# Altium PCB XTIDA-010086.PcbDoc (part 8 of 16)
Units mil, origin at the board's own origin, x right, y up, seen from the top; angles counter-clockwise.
Board outline 14763.78 x 8267.72 mil, 6 copper layers (Top Layer, GND Layer, Signal Layer 1, Signal Layer 2, Power Layer, Bottom Layer), stack 62 mil thick; 1933 components, 1002 nets, 4886 pads, 6482 vias.
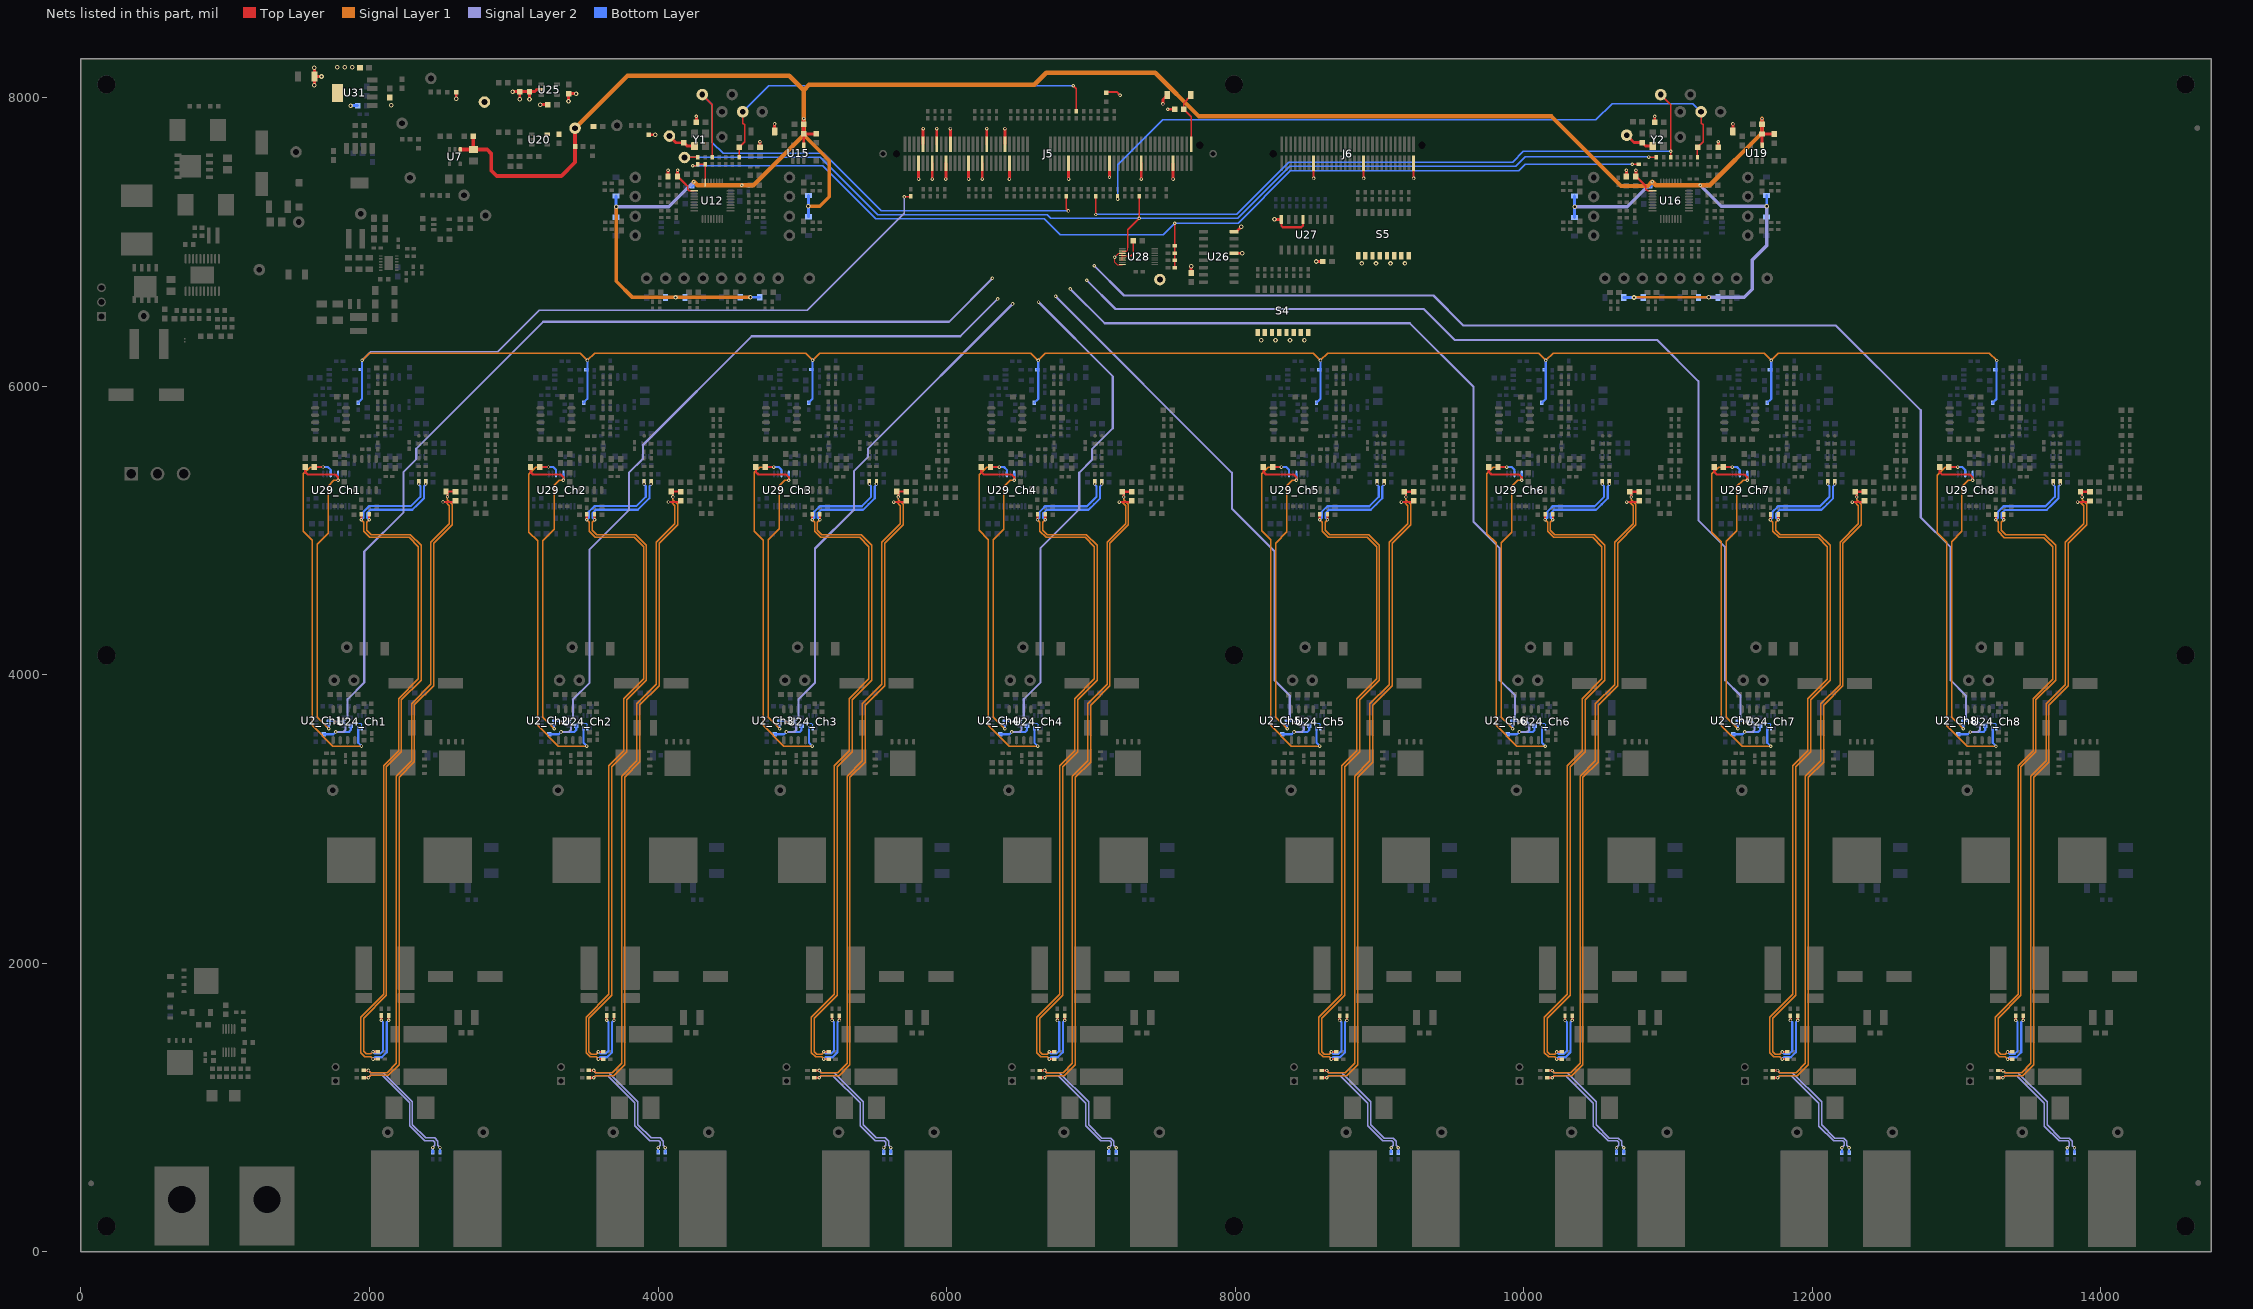
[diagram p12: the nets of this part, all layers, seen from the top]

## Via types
v1: diameter 32, hole 16, Top Layer to Bottom Layer, tented both sides, 4685 vias
v2: diameter 24, hole 12, Top Layer to Bottom Layer, tented both sides, 1013 vias
v3: diameter 32, hole 16, Top Layer to Bottom Layer, 728 vias
v4: diameter 19.68, hole 7.87, Top Layer to Bottom Layer, 40 vias
v5: diameter 214.57, hole 140, Top Layer to Bottom Layer, 16 vias

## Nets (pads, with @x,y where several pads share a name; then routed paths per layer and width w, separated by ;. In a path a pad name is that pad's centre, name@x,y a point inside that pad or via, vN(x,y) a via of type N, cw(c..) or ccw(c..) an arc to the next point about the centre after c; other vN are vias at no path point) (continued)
AVDD: C79.1 C80.1 C100.1 C101.1 C103.1 C129.1 D12.1 D16.1 D19.1 D20.1 D21.1 D22.1 D23.1 D24.1 D25.1 D26.1 D27.1 D28.1 D29.1 D30.1 D31.1 D32.1 R115.1 R119.1 R146.1 R150.1 R177.2 R180.1 R181.2 R184.2 R203.1 TP24.1 U7.1 U15.4 U19.4 U20.5 | length 18806.3
  Top Layer w20: v2(5009.33,7853.48) C79.1@5009.33,7813.48 C80.1@5009.33,7747.48 ; U15.4@5009.73,7668.61 5009.73,7747.08 C80.1@5009.33,7747.48 ; R177.2@5096,7748.5 5094.98,7747.48 C80.1@5009.33,7747.48 ; v2(11651.01,7853.19) C100.1@11651.01,7813.19 11651.01,7747.19 C101.1@11651.41,7746.79 ; U19.4@11651.41,7668.32 C101.1@11651.41,7746.79 ; R181.2@11737.06,7746.79 C101.1@11651.41,7746.79
  Top Layer w25: U7.1@2629.4,7639.52 C129.1@2719.8,7639.52 ; R184.2@2720.5,7731.32 2720.5,7640.21 C129.1@2719.8,7639.52 ; TP24.1@3425,7787 R180.1@3425,7660 3425,7550.31 3330.69,7456 2882.85,7456 2843,7495.85 2843,7612 2815.68,7639.32 C129.1@2720,7639.32 C129.1@2719.8,7639.52
  Signal Layer 1 w20: v1(10763.53,6613.86) 10764.89,6615.22 v1(11282.02,6615.22)
  Signal Layer 1 w25: v1(3710,7243) 3710,6727 3822.83,6614.17 v1(4121.83,6614.17) 4123.19,6615.54 v1(4640.32,6615.54) ; 5009.33,7740.33 5186,7563.66 5186,7311 5120.5,7245.5 v1(5041.93,7245.5)
  Signal Layer 1 w30: TP24.1@3425,7787 3788,8150 4910,8150 5009.33,8050.67 ; v2(4248.53,7416.63) 4272.91,7392.26 v2(4580.91,7392.26) 4661.26,7392.26 5009.33,7740.33 v2(5009.33,7853.48) 5009.33,8050.67 ; v2(11651.01,7853.19) 11651.01,7754.01 11288.94,7391.94 v2(11222.61,7391.94) 10914.61,7391.94 v2(10890.23,7416.32) 10860.91,7387 10674,7387 10192,7869 7749.64,7869 7446.64,8172 6691,8172 6607,8088 5046.66,8088 5009.33,8050.67
  Signal Layer 2 w25: v1(3710,7243) 4074.89,7243 v2(4248.53,7416.63) ; v1(10352.7,7241.69) 10717.6,7241.69 v2@10891.23,7415.32 ; v2(11222.61,7391.94) 11369.37,7245.18 v1(11683.63,7245.18) 11683.63,6973.63 11584,6874 11584,6671 11528.22,6615.22 v1(11282.02,6615.22)
  Bottom Layer w20: D16.1@3710,7170.47 v1(3710,7243) D12.1@3710,7318.06 ; D19.1@4051.05,6614.17 v1(4121.83,6614.17) D20.1@4186.24,6614.17 ; R115.1@4236.15,7382.63 4248.53,7395.01 v2(4248.53,7416.63) ; D21.1@4569.55,6615.54 v1(4640.32,6615.54) D22.1@4704.74,6615.54 ; v2(4580.91,7392.26) R119.1@4624.53,7392.26 ; D23.1@5041.93,7172.96 v1(5041.93,7245.5) D24.1@5041.93,7320.56 ; D26.1@10352.7,7169.15 v1(10352.7,7241.69) D25.1@10352.7,7316.75 ; D27.1@10692.75,6613.86 v1(10763.53,6613.86) D28.1@10827.94,6613.86 ; R146.1@10877.85,7382.32 10890.23,7394.7 v2(10890.23,7416.32) ; D29.1@11211.25,6615.22 v1(11282.02,6615.22) D30.1@11346.44,6615.22 ; v2(11222.61,7391.94) R150.1@11266.23,7391.94 ; D31.1@11683.63,7172.65 v1(11683.63,7245.18) D32.1@11683.63,7320.24
B+_Ch1: C52_Ch1.1 R10_Ch1.1 R14_Ch1.1 R64_Ch1.1 | length 5320.5
  Top Layer w15: R14_Ch1.1@1959.25,1207 v2(1992.97,1207) ; v2(2541,5232) 2541,5258.35 C52_Ch1.1@2530.54,5268.8 2595.54,5268.8 R64_Ch1.1@2596.05,5268.3
  Signal Layer 1 w10: v2(1992.97,1207) 2007.97,1222 2130.28,1222 2206,1297.72 2206,3288.72 2312,3394.72 2312,3789.72 2446,3923.72 2446,4910.72 2574,5038.72 2574,5180.14 2541,5213.14 v2(2541,5232)
  Signal Layer 2 w10: v2(1992.97,1207) 2007.97,1222 2088,1222 2278.43,1031.57 2278.43,872.29 2381.72,769 2444,769 2454,759 2454,737.34 v2(2439,722.34)
  Bottom Layer w15: R10_Ch1.1@2439,688.62 v2(2439,722.34)
B+_Ch2: C52_Ch2.1 R10_Ch2.1 R14_Ch2.1 R64_Ch2.1 | length 5320.5
  Top Layer w15: R14_Ch2.1@3521.25,1206.92 v2(3554.97,1206.92) ; v2(4103.5,5231.42) 4103.5,5257.76 4093.05,5268.22 R64_Ch2.1@4158.05,5268.22 R64_Ch2.1@4158.55,5267.72
  Signal Layer 1 w10: v2(3554.97,1206.92) 3569.97,1221.92 3692.28,1221.92 3768,1297.64 3768,3288.64 3874,3394.64 3874,3789.64 4008,3923.64 4008,4910.64 4136,5038.64 4136,5180.06 4103,5213.06 v2@4103,5231.92
  Signal Layer 2 w10: v2(3554.97,1206.92) 3569.97,1221.92 3650,1221.92 3840.43,1031.5 3840.43,872.21 3943.72,768.92 4006,768.92 4016,758.92 4016,737.26 v2(4001,722.26)
  Bottom Layer w15: R10_Ch2.1@4001,688.54 v2(4001,722.26)
B+_Ch3: C52_Ch3.1 R10_Ch3.1 R14_Ch3.1 R64_Ch3.1 | length 5320.5
  Top Layer w15: R14_Ch3.1@5083.25,1206.84 v2(5116.97,1206.84) ; v2(5665.5,5231.34) 5665.5,5257.69 5655.05,5268.14 R64_Ch3.1@5720.05,5268.14 R64_Ch3.1@5720.55,5267.64
  Signal Layer 1 w10: v2(5116.97,1206.84) 5131.97,1221.84 5254.28,1221.84 5330,1297.56 5330,3288.56 5436,3394.56 5436,3789.56 5570,3923.56 5570,4910.56 5698,5038.56 5698,5179.98 5665,5212.98 v2@5665,5231.84
  Signal Layer 2 w10: v2(5116.97,1206.84) 5131.97,1221.84 5212,1221.84 5402.43,1031.42 5402.43,872.13 5505.72,768.84 5568,768.84 5578,758.84 5578,737.18 v2(5563,722.18)
  Bottom Layer w15: R10_Ch3.1@5563,688.46 v2(5563,722.18)
B+_Ch4: C52_Ch4.1 R10_Ch4.1 R14_Ch4.1 R64_Ch4.1 | length 5320.5
  Top Layer w15: R14_Ch4.1@6645.25,1206.76 v2(6678.97,1206.76) ; v2(7227.5,5231.26) 7227.5,5257.61 7217.05,5268.06 R64_Ch4.1@7282.05,5268.06 R64_Ch4.1@7282.55,5267.56
  Signal Layer 1 w10: v2(6678.97,1206.76) 6693.97,1221.76 6816.28,1221.76 6892,1297.48 6892,3288.48 6998,3394.48 6998,3789.48 7132,3923.48 7132,4910.48 7260,5038.48 7260,5179.91 7227,5212.91 v2@7227,5231.76
  Signal Layer 2 w10: v2(6678.97,1206.76) 6693.97,1221.76 6774,1221.76 6964.43,1031.34 6964.43,872.05 7067.72,768.76 7130,768.76 7140,758.76 7140,737.1 v2(7125,722.1)
  Bottom Layer w15: R10_Ch4.1@7125,688.39 v2(7125,722.1)
B+_Ch5: C52_Ch5.1 R10_Ch5.1 R14_Ch5.1 R64_Ch5.1 | length 5320.5
  Top Layer w15: R14_Ch5.1@8600.95,1206.69 v2(8634.67,1206.69) ; v2(9183.2,5231.18) 9183.2,5257.53 9172.75,5267.98 R64_Ch5.1@9237.75,5267.98 R64_Ch5.1@9238.25,5267.48
  Signal Layer 1 w10: v2(8634.67,1206.69) 8649.67,1221.69 8771.99,1221.69 8847.7,1297.4 8847.7,3288.4 8953.7,3394.4 8953.7,3789.4 9087.7,3923.4 9087.7,4910.4 9215.7,5038.4 9215.7,5179.83 9182.7,5212.83 v2@9182.7,5231.69
  Signal Layer 2 w10: v2(8634.67,1206.69) 8649.67,1221.69 8729.7,1221.69 8920.13,1031.26 8920.13,871.98 9023.42,768.69 9085.7,768.69 9095.7,758.69 9095.7,737.02 v2(9080.7,722.02)
  Bottom Layer w15: R10_Ch5.1@9080.7,688.31 v2(9080.7,722.02)
B+_Ch6: C52_Ch6.1 R10_Ch6.1 R14_Ch6.1 R64_Ch6.1 | length 5320.5
  Top Layer w15: R14_Ch6.1@10162.95,1206.61 v2(10196.67,1206.61) ; v2(10745.2,5231.1) 10745.2,5257.45 10734.75,5267.91 R64_Ch6.1@10799.75,5267.91 R64_Ch6.1@10800.25,5267.4
  Signal Layer 1 w10: v2(10196.67,1206.61) 10211.67,1221.61 10333.99,1221.61 10409.7,1297.32 10409.7,3288.32 10515.7,3394.32 10515.7,3789.32 10649.7,3923.32 10649.7,4910.32 10777.7,5038.32 10777.7,5179.75 10744.7,5212.75 v2@10744.7,5231.61
  Signal Layer 2 w10: v2(10196.67,1206.61) 10211.67,1221.61 10291.7,1221.61 10482.13,1031.18 10482.13,871.9 10585.42,768.61 10647.7,768.61 10657.7,758.61 10657.7,736.95 v2(10642.7,721.95)
  Bottom Layer w15: R10_Ch6.1@10642.7,688.23 v2(10642.7,721.95)
B+_Ch7: C52_Ch7.1 R10_Ch7.1 R14_Ch7.1 R64_Ch7.1 | length 5320.5
  Top Layer w15: R14_Ch7.1@11724.95,1206.53 v2(11758.67,1206.53) ; v2(12307.2,5231.02) 12307.2,5257.37 12296.75,5267.83 R64_Ch7.1@12361.75,5267.83 R64_Ch7.1@12362.25,5267.32
  Signal Layer 1 w10: v2(11758.67,1206.53) 11773.67,1221.53 11895.99,1221.53 11971.7,1297.24 11971.7,3288.24 12077.7,3394.24 12077.7,3789.24 12211.7,3923.24 12211.7,4910.24 12339.7,5038.24 12339.7,5179.67 12306.7,5212.67 v2@12306.7,5231.53
  Signal Layer 2 w10: v2(11758.67,1206.53) 11773.67,1221.53 11853.7,1221.53 12044.13,1031.1 12044.13,871.82 12147.42,768.53 12209.7,768.53 12219.7,758.53 12219.7,736.87 v2(12204.7,721.87)
  Bottom Layer w15: R10_Ch7.1@12204.7,688.15 v2(12204.7,721.87)
B+_Ch8: C52_Ch8.1 R10_Ch8.1 R14_Ch8.1 R64_Ch8.1 | length 5320.5
  Top Layer w15: R14_Ch8.1@13286.95,1206.45 v2(13320.67,1206.45) ; v2(13869.2,5230.95) 13869.2,5257.29 13858.75,5267.75 R64_Ch8.1@13923.75,5267.75 R64_Ch8.1@13924.25,5267.24
  Signal Layer 1 w10: v2(13320.67,1206.45) 13335.67,1221.45 13457.99,1221.45 13533.7,1297.16 13533.7,3288.16 13639.7,3394.16 13639.7,3789.16 13773.7,3923.16 13773.7,4910.16 13901.7,5038.16 13901.7,5179.59 13868.7,5212.59 v2@13868.7,5231.45
  Signal Layer 2 w10: v2(13320.67,1206.45) 13335.67,1221.45 13415.7,1221.45 13606.13,1031.02 13606.13,871.74 13709.42,768.45 13771.7,768.45 13781.7,758.45 13781.7,736.79 v2(13766.7,721.79)
  Bottom Layer w15: R10_Ch8.1@13766.7,688.07 v2(13766.7,721.79)
B-_Ch1: R17_Ch1.1 R20_Ch1.2 R70_Ch1.1 | length 5283.3
  Top Layer w15: R17_Ch1.1@1959.25,1257 v2(1992.97,1257) ; v2(2510,5197) 2588.75,5197 R70_Ch1.1@2596.05,5204.3
  Signal Layer 1 w10: v2(1992.97,1257) 2007.97,1242 2122,1242 2186,1306 2186,3297 2292,3403 2292,3798 2426,3932 2426,4919 2554,5047 2554,5171.86 2528.86,5197 v2(2510,5197)
  Signal Layer 2 w10: v2(1992.97,1257) 2007.97,1242 2096.28,1242 2298.43,1039.86 2298.43,880.57 2390,789 2452.28,789 2474,767.28 2474,737.34 v2(2489,722.34)
  Bottom Layer w15: R20_Ch1.2@2489,688.62 v2(2489,722.34)
B-_Ch2: R17_Ch2.1 R20_Ch2.2 R70_Ch2.1 | length 5283.3
  Top Layer w15: R17_Ch2.1@3521.25,1256.92 v2(3554.97,1256.92) ; v2(4072.5,5196.42) 4151.25,5196.42 R70_Ch2.1@4158.55,5203.72
  Signal Layer 1 w10: v2(3554.97,1256.92) 3569.97,1241.92 3684,1241.92 3748,1305.92 3748,3296.92 3854,3402.92 3854,3797.92 3988,3931.92 3988,4918.92 4116,5046.92 4116,5171.78 4090.86,5196.92 v2@4072,5196.92
  Signal Layer 2 w10: v2(3554.97,1256.92) 3569.97,1241.92 3658.28,1241.92 3860.43,1039.78 3860.43,880.5 3952,788.92 4014.28,788.92 4036,767.21 4036,737.26 v2(4051,722.26)
  Bottom Layer w15: R20_Ch2.2@4051,688.54 v2(4051,722.26)
B-_Ch3: R17_Ch3.1 R20_Ch3.2 R70_Ch3.1 | length 5283.3
  Top Layer w15: R17_Ch3.1@5083.25,1256.84 v2(5116.97,1256.84) ; v2(5634.5,5196.34) 5713.25,5196.34 R70_Ch3.1@5720.55,5203.64
  Signal Layer 1 w10: v2(5116.97,1256.84) 5131.97,1241.84 5246,1241.84 5310,1305.84 5310,3296.84 5416,3402.84 5416,3797.84 5550,3931.84 5550,4918.84 5678,5046.84 5678,5171.7 5652.86,5196.84 v2@5634,5196.84
  Signal Layer 2 w10: v2(5116.97,1256.84) 5131.97,1241.84 5220.28,1241.84 5422.43,1039.7 5422.43,880.42 5514,788.84 5576.28,788.84 5598,767.13 5598,737.18 v2(5613,722.18)
  Bottom Layer w15: R20_Ch3.2@5613,688.46 v2(5613,722.18)
B-_Ch4: R17_Ch4.1 R20_Ch4.2 R70_Ch4.1 | length 5283.3
  Top Layer w15: R17_Ch4.1@6645.25,1256.76 v2(6678.97,1256.76) ; v2(7196.5,5196.26) 7275.25,5196.26 R70_Ch4.1@7282.55,5203.56
  Signal Layer 1 w10: v2(6678.97,1256.76) 6693.97,1241.76 6808,1241.76 6872,1305.76 6872,3296.76 6978,3402.76 6978,3797.76 7112,3931.76 7112,4918.76 7240,5046.76 7240,5171.62 7214.86,5196.76 v2@7196,5196.76
  Signal Layer 2 w10: v2(6678.97,1256.76) 6693.97,1241.76 6782.28,1241.76 6984.43,1039.62 6984.43,880.34 7076,788.76 7138.28,788.76 7160,767.05 7160,737.1 v2(7175,722.1)
  Bottom Layer w15: R20_Ch4.2@7175,688.39 v2(7175,722.1)
B-_Ch5: R17_Ch5.1 R20_Ch5.2 R70_Ch5.1 | length 5283.3
  Top Layer w15: R17_Ch5.1@8600.95,1256.69 v2(8634.67,1256.69) ; v2(9152.2,5196.18) 9230.95,5196.18 R70_Ch5.1@9238.25,5203.48
  Signal Layer 1 w10: v2(8634.67,1256.69) 8649.67,1241.69 8763.7,1241.69 8827.7,1305.69 8827.7,3296.69 8933.7,3402.69 8933.7,3797.69 9067.7,3931.69 9067.7,4918.69 9195.7,5046.69 9195.7,5171.54 9170.56,5196.69 v2@9151.7,5196.69
  Signal Layer 2 w10: v2(8634.67,1256.69) 8649.67,1241.69 8737.99,1241.69 8940.13,1039.54 8940.13,880.26 9031.7,788.69 9093.99,788.69 9115.7,766.97 9115.7,737.02 v2(9130.7,722.02)
  Bottom Layer w15: R20_Ch5.2@9130.7,688.31 v2(9130.7,722.02)
B-_Ch6: R17_Ch6.1 R20_Ch6.2 R70_Ch6.1 | length 5283.3
  Top Layer w15: R17_Ch6.1@10162.95,1256.61 v2(10196.67,1256.61) ; v2(10714.2,5196.1) 10792.95,5196.1 R70_Ch6.1@10800.25,5203.4
  Signal Layer 1 w10: v2(10196.67,1256.61) 10211.67,1241.61 10325.7,1241.61 10389.7,1305.61 10389.7,3296.61 10495.7,3402.61 10495.7,3797.61 10629.7,3931.61 10629.7,4918.61 10757.7,5046.61 10757.7,5171.46 10732.56,5196.61 v2@10713.7,5196.61
  Signal Layer 2 w10: v2(10196.67,1256.61) 10211.67,1241.61 10299.99,1241.61 10502.13,1039.47 10502.13,880.18 10593.7,788.61 10655.99,788.61 10677.7,766.89 10677.7,736.95 v2(10692.7,721.95)
  Bottom Layer w15: R20_Ch6.2@10692.7,688.23 v2(10692.7,721.95)
B-_Ch7: R17_Ch7.1 R20_Ch7.2 R70_Ch7.1 | length 5283.3
  Top Layer w15: R17_Ch7.1@11724.95,1256.53 v2(11758.67,1256.53) ; v2(12276.2,5196.02) 12354.95,5196.02 R70_Ch7.1@12362.25,5203.32
  Signal Layer 1 w10: v2(11758.67,1256.53) 11773.67,1241.53 11887.7,1241.53 11951.7,1305.53 11951.7,3296.53 12057.7,3402.53 12057.7,3797.53 12191.7,3931.53 12191.7,4918.53 12319.7,5046.53 12319.7,5171.39 12294.56,5196.53 v2@12275.7,5196.53
  Signal Layer 2 w10: v2(11758.67,1256.53) 11773.67,1241.53 11861.99,1241.53 12064.13,1039.39 12064.13,880.1 12155.7,788.53 12217.99,788.53 12239.7,766.81 12239.7,736.87 v2(12254.7,721.87)
  Bottom Layer w15: R20_Ch7.2@12254.7,688.15 v2(12254.7,721.87)
B-_Ch8: R17_Ch8.1 R20_Ch8.2 R70_Ch8.1 | length 5283.3
  Top Layer w15: R17_Ch8.1@13286.95,1256.45 v2(13320.67,1256.45) ; v2(13838.2,5195.95) 13916.95,5195.95 R70_Ch8.1@13924.25,5203.24
  Signal Layer 1 w10: v2(13320.67,1256.45) 13335.67,1241.45 13449.7,1241.45 13513.7,1305.45 13513.7,3296.45 13619.7,3402.45 13619.7,3797.45 13753.7,3931.45 13753.7,4918.45 13881.7,5046.45 13881.7,5171.31 13856.56,5196.45 v2@13837.7,5196.45
  Signal Layer 2 w10: v2(13320.67,1256.45) 13335.67,1241.45 13423.99,1241.45 13626.13,1039.31 13626.13,880.02 13717.7,788.45 13779.99,788.45 13801.7,766.73 13801.7,736.79 v2(13816.7,721.79)
  Bottom Layer w15: R20_Ch8.2@13816.7,688.07 v2(13816.7,721.79)
C2000_CLK: R95.2 R126.2 R292.1 TP11.1 U28.2 | length 7626.3
  Top Layer w6: U28.2@7218,6935.76 7247.25,6935.76 7256,6944.51 7256,6959.65
  Top Layer w10: TP11.1@4183.11,7584.01 4274.49,7584.01 R95.2@4275.11,7584.63 ; 7256,6959.65 7256,7082 v2(7336,7162) R292.1@7336,7316.38 ; v2(10866,7587) 10914.14,7587 R126.2@10916.82,7584.32
  Bottom Layer w10: TP11.1@4183.11,7584.01 5125.99,7584.01 5524.3,7185.7 5524.6,7186 6697.62,7186 6721.62,7162 v2(7336,7162) 8018,7162 8379,7523 9944,7523 10009.83,7588.83 10864.17,7588.83 v2(10866,7587)
C2000_RESET2: C126.1 J5.120 S6.1 | length 383.6
  Top Layer w10: S6.1@7692.37,8017.7 7692.37,8010.39 7642.73,7960.76 7642.73,7918.85 C126.1@7643.51,7918.07 7695.51,7866.07 J5.120@7695.51,7676.56
CLK_Counter: R54.2 R55.2 R56.2 R57.2 R95.1 R97.1 R187.2 U12.23 | length 7483.9
  Top Layer w10: v2(4240,7527) 4264.73,7527 R95.1@4275.11,7537.39 R97.1@4328.11,7537.39 4327.9,7537.18 U12.23@4327.9,7410 ; v2(7581,7128) 7581.62,7127.38 R54.2@7581.62,6971.01 R55.2@7581.62,6921.01 R56.2@7581.62,6871.01 R57.2@7581.62,6821.01 ; v2(10752,7537.39) 10752.53,7536.86 R187.2@10795.38,7536.86
  Bottom Layer w10: v2(4240,7527) 4241,7526 5142,7526 5509,7159 6675,7159 6786,7048 7501,7048 v2(7581,7128) 7582.96,7129.96 8019.96,7129.96 8383,7493 9966,7493 10010.39,7537.39 v2(10752,7537.39)
CS1: R108.1 R112.2 R280.1 TP16.1 | length 2889.6
  Top Layer w10: R112.2@4562.11,7584.63 4562.11,7654.52 R108.1@4563.11,7655.52 4600.53,7692.93 4600.53,7809.63 4587.11,7823.05 TP16.1@4587.11,7901.01 ; v2(6877,8081) 6898.78,8059.22 R280.1@6898.78,7903.32
  Bottom Layer w10: TP16.1@4587.11,7901.01 4767.8,8081.7 4768.5,8081 v2(6877,8081)
CS2: R139.1 R143.2 R285.2 TP22.1 | length 4839.8
  Top Layer w10: R285.2@7184.65,7316.38 7184.65,7296.35 v2(7185,7296) ; R143.2@11203.82,7584.32 11203.82,7654.2 11242.23,7692.61 11242.23,7809.32 11228.82,7822.73 TP22.1@11228.82,7900.7
  Bottom Layer w10: v2(7185,7296) 7185,7533.29 7184.65,7533.65 7497,7846 10500,7846 10612,7958 11171.51,7958 TP22.1@11228.82,7900.7
CS+_Ch1: R12_Ch1.1 R15_Ch1.1 R22_Ch1.1 R29_Ch1.1 R45_Ch1.1 | length 5266.5
  Top Layer w15: v2(1998,5073.28) R29_Ch1.1@1998,5110.43 ; v2(2025,1386) R15_Ch1.1@2058.72,1386 ; v2(2082,1604) R12_Ch1.1@2082,1637.72
  Signal Layer 1 w10: v2(1998,5073.28) 1981,5056.28 1981,5002 2012,4971 2283,4971 2358,4896 2358,3962 2222,3826 2222,3465 2118,3361 2118,1777.72 1959,1618.72 1959,1388.28 1976.28,1371 2010,1371 v2(2025,1386)
  Bottom Layer w15: v2(1998,5073.28) 1983.5,5087.78 1983.5,5118.2 2008,5142.7 2297.76,5142.7 2336.76,5181.7 2378,5222.94 2378,5305.18 2390,5317.18 R45_Ch1.1@2390,5340.43 ; v2(2025,1386) 2037.5,1373.5 2074.5,1373.5 2095,1394 2095,1591 v2(2082,1604)
  other v2: 2390,5322
CS+_Ch2: R12_Ch2.1 R15_Ch2.1 R22_Ch2.1 R29_Ch2.1 R45_Ch2.1 | length 5266.5
  Top Layer w15: v2(3560,5073.2) R29_Ch2.1@3560,5110.35 ; v2(3587,1385.92) R15_Ch2.1@3620.72,1385.92 ; v2(3644,1603.92) R12_Ch2.1@3644,1637.64
  Signal Layer 1 w10: v2(3560,5073.2) 3543,5056.2 3543,5001.92 3574,4970.92 3845,4970.92 3920,4895.92 3920,3961.92 3784,3825.92 3784,3464.92 3680,3360.92 3680,1777.64 3521,1618.64 3521,1388.21 3538.28,1370.92 3572,1370.92 v2(3587,1385.92)
  Bottom Layer w15: v2(3560,5073.2) 3545.5,5087.7 3545.5,5118.12 3570,5142.62 3859.76,5142.62 3898.76,5181.62 3940,5222.86 3940,5305.1 3952,5317.1 R45_Ch2.1@3952,5340.35 ; v2(3587,1385.92) 3599.5,1373.42 3636.5,1373.42 3657,1393.92 3657,1590.92 v2(3644,1603.92)
  other v2: 3952,5321.92
CS+_Ch3: R12_Ch3.1 R15_Ch3.1 R22_Ch3.1 R29_Ch3.1 R45_Ch3.1 | length 5266.5
  Top Layer w15: v2(5122,5073.13) R29_Ch3.1@5122,5110.27 ; v2(5149,1385.84) R15_Ch3.1@5182.72,1385.84 ; v2(5206,1603.84) R12_Ch3.1@5206,1637.56
  Signal Layer 1 w10: v2(5122,5073.13) 5105,5056.13 5105,5001.84 5136,4970.84 5407,4970.84 5482,4895.84 5482,3961.84 5346,3825.84 5346,3464.84 5242,3360.84 5242,1777.56 5083,1618.56 5083,1388.13 5100.28,1370.84 5134,1370.84 v2(5149,1385.84)
  Bottom Layer w15: v2(5122,5073.13) 5107.5,5087.63 5107.5,5118.04 5132,5142.54 5421.76,5142.54 5460.76,5181.54 5502,5222.78 5502,5305.02 5514,5317.02 R45_Ch3.1@5514,5340.27 ; v2(5149,1385.84) 5161.5,1373.34 5198.5,1373.34 5219,1393.84 5219,1590.84 v2(5206,1603.84)
  other v2: 5514,5321.84
CS+_Ch4: R12_Ch4.1 R15_Ch4.1 R22_Ch4.1 R29_Ch4.1 R45_Ch4.1 | length 5266.5
  Top Layer w15: v2(6684,5073.05) R29_Ch4.1@6684,5110.19 ; v2(6711,1385.76) R15_Ch4.1@6744.72,1385.76 ; v2(6768,1603.76) R12_Ch4.1@6768,1637.48
  Signal Layer 1 w10: v2(6684,5073.05) 6667,5056.05 6667,5001.76 6698,4970.76 6969,4970.76 7044,4895.76 7044,3961.76 6908,3825.76 6908,3464.76 6804,3360.76 6804,1777.48 6645,1618.48 6645,1388.05 6662.28,1370.76 6696,1370.76 v2(6711,1385.76)
  Bottom Layer w15: v2(6684,5073.05) 6669.5,5087.55 6669.5,5117.96 6694,5142.46 6983.76,5142.46 7022.76,5181.46 7064,5222.7 7064,5304.94 7076,5316.94 R45_Ch4.1@7076,5340.19 ; v2(6711,1385.76) 6723.5,1373.26 6760.5,1373.26 6781,1393.76 6781,1590.76 v2(6768,1603.76)
  other v2: 7076,5321.76
CS+_Ch5: R12_Ch5.1 R15_Ch5.1 R22_Ch5.1 R29_Ch5.1 R45_Ch5.1 | length 5266.5
  Top Layer w15: v2(8639.7,5072.97) R29_Ch5.1@8639.7,5110.11 ; v2(8666.7,1385.69) R15_Ch5.1@8700.42,1385.69 ; v2(8723.7,1603.69) R12_Ch5.1@8723.7,1637.4
  Signal Layer 1 w10: v2(8639.7,5072.97) 8622.7,5055.97 8622.7,5001.69 8653.7,4970.69 8924.7,4970.69 8999.7,4895.69 8999.7,3961.69 8863.7,3825.69 8863.7,3464.69 8759.7,3360.69 8759.7,1777.4 8600.7,1618.4 8600.7,1387.97 8617.99,1370.69 8651.7,1370.69 v2(8666.7,1385.69)
  Bottom Layer w15: v2(8639.7,5072.97) 8625.2,5087.47 8625.2,5117.89 8649.7,5142.39 8939.47,5142.39 8978.47,5181.39 9019.7,5222.62 9019.7,5304.86 9031.7,5316.86 R45_Ch5.1@9031.7,5340.11 ; v2(8666.7,1385.69) 8679.2,1373.19 8716.2,1373.19 8736.7,1393.69 8736.7,1590.69 v2(8723.7,1603.69)
  other v2: 9031.7,5321.69
CS+_Ch6: R12_Ch6.1 R15_Ch6.1 R22_Ch6.1 R29_Ch6.1 R45_Ch6.1 | length 5266.5
  Top Layer w15: v2(10201.7,5072.89) R29_Ch6.1@10201.7,5110.03 ; v2(10228.7,1385.61) R15_Ch6.1@10262.42,1385.61 ; v2(10285.7,1603.61) R12_Ch6.1@10285.7,1637.32
  Signal Layer 1 w10: v2(10201.7,5072.89) 10184.7,5055.89 10184.7,5001.61 10215.7,4970.61 10486.7,4970.61 10561.7,4895.61 10561.7,3961.61 10425.7,3825.61 10425.7,3464.61 10321.7,3360.61 10321.7,1777.32 10162.7,1618.32 10162.7,1387.89 10179.99,1370.61 10213.7,1370.61 v2(10228.7,1385.61)
  Bottom Layer w15: v2(10201.7,5072.89) 10187.2,5087.39 10187.2,5117.81 10211.7,5142.31 10501.47,5142.31 10540.47,5181.31 10581.7,5222.54 10581.7,5304.78 10593.7,5316.78 R45_Ch6.1@10593.7,5340.03 ; v2(10228.7,1385.61) 10241.2,1373.11 10278.2,1373.11 10298.7,1393.61 10298.7,1590.61 v2(10285.7,1603.61)
  other v2: 10593.7,5321.61
CS+_Ch7: R12_Ch7.1 R15_Ch7.1 R22_Ch7.1 R29_Ch7.1 R45_Ch7.1 | length 5266.5
  Top Layer w15: v2(11763.7,5072.81) R29_Ch7.1@11763.7,5109.95 ; v2(11790.7,1385.53) R15_Ch7.1@11824.42,1385.53 ; v2(11847.7,1603.53) R12_Ch7.1@11847.7,1637.24
  Signal Layer 1 w10: v2(11763.7,5072.81) 11746.7,5055.81 11746.7,5001.53 11777.7,4970.53 12048.7,4970.53 12123.7,4895.53 12123.7,3961.53 11987.7,3825.53 11987.7,3464.53 11883.7,3360.53 11883.7,1777.24 11724.7,1618.24 11724.7,1387.81 11741.99,1370.53 11775.7,1370.53 v2(11790.7,1385.53)
  Bottom Layer w15: v2(11763.7,5072.81) 11749.2,5087.31 11749.2,5117.73 11773.7,5142.23 12063.47,5142.23 12102.47,5181.23 12143.7,5222.46 12143.7,5304.7 12155.7,5316.7 R45_Ch7.1@12155.7,5339.95 ; v2(11790.7,1385.53) 11803.2,1373.03 11840.2,1373.03 11860.7,1393.53 11860.7,1590.53 v2(11847.7,1603.53)
  other v2: 12155.7,5321.53
CS+_Ch8: R12_Ch8.1 R15_Ch8.1 R22_Ch8.1 R29_Ch8.1 R45_Ch8.1 | length 5266.5
  Top Layer w15: v2(13325.7,5072.73) R29_Ch8.1@13325.7,5109.87 ; v2(13352.7,1385.45) R15_Ch8.1@13386.42,1385.45 ; v2(13409.7,1603.45) R12_Ch8.1@13409.7,1637.17
  Signal Layer 1 w10: v2(13325.7,5072.73) 13308.7,5055.73 13308.7,5001.45 13339.7,4970.45 13610.7,4970.45 13685.7,4895.45 13685.7,3961.45 13549.7,3825.45 13549.7,3464.45 13445.7,3360.45 13445.7,1777.16 13286.7,1618.16 13286.7,1387.73 13303.99,1370.45 13337.7,1370.45 v2(13352.7,1385.45)
  Bottom Layer w15: v2(13325.7,5072.73) 13311.2,5087.23 13311.2,5117.65 13335.7,5142.15 13625.47,5142.15 13664.47,5181.15 13705.7,5222.39 13705.7,5304.63 13717.7,5316.63 R45_Ch8.1@13717.7,5339.87 ; v2(13352.7,1385.45) 13365.2,1372.95 13402.2,1372.95 13422.7,1393.45 13422.7,1590.45 v2(13409.7,1603.45)
  other v2: 13717.7,5321.45
CS-_Ch1: R13_Ch1.1 R16_Ch1.1 R26_Ch1.1 R28_Ch1.1 R47_Ch1.1 | length 5341
  Top Layer w15: v2(1944,5073.28) R28_Ch1.1@1944,5110.43 ; v2(2025,1336) R16_Ch1.1@2058.72,1336 ; v2(2133,1604) R13_Ch1.1@2133,1637.72
  Signal Layer 1 w10: v2(1944,5073.28) 1961,5056.28 1961,4993.72 2003.72,4951 2274.72,4951 2338,4887.72 2338,3970.28 2202,3834.28 2202,3473.28 2098,3369.28 2098,1786 1939,1627 1939,1380 1968,1351 2010,1351 v2(2025,1336)
  Bottom Layer w15: v2(1944,5073.28) 1958.5,5087.78 1958.5,5128.56 1990.32,5160.38 1997.64,5167.7 2287.41,5167.7 2353,5233.29 2353,5305.18 2341,5317.18 R47_Ch1.1@2341,5340.43 ; v2(2025,1336) 2037.5,1348.5 2084.86,1348.5 2120,1383.64 2120,1591 v2(2133,1604)
  other v2: 2341,5322
CS-_Ch2: R13_Ch2.1 R16_Ch2.1 R26_Ch2.1 R28_Ch2.1 R47_Ch2.1 | length 5341
  Top Layer w15: v2(3506,5073.2) R28_Ch2.1@3506,5110.35 ; v2(3587,1335.92) R16_Ch2.1@3620.72,1335.92 ; v2(3695,1603.92) R13_Ch2.1@3695,1637.64
  Signal Layer 1 w10: v2(3506,5073.2) 3523,5056.2 3523,4993.64 3565.72,4950.92 3836.72,4950.92 3900,4887.64 3900,3970.21 3764,3834.21 3764,3473.21 3660,3369.21 3660,1785.92 3501,1626.92 3501,1379.92 3530,1350.92 3572,1350.92 v2(3587,1335.92)
  Bottom Layer w15: v2(3506,5073.2) 3520.5,5087.7 3520.5,5128.48 3552.32,5160.3 3559.64,5167.62 3849.41,5167.62 3915,5233.21 3915,5305.1 3903,5317.1 R47_Ch2.1@3903,5340.35 ; v2(3587,1335.92) 3599.5,1348.42 3646.86,1348.42 3682,1383.57 3682,1590.92 v2(3695,1603.92)
  other v2: 3903,5321.92
CS-_Ch3: R13_Ch3.1 R16_Ch3.1 R26_Ch3.1 R28_Ch3.1 R47_Ch3.1 | length 5341
  Top Layer w15: v2(5068,5073.13) R28_Ch3.1@5068,5110.27 ; v2(5149,1335.84) R16_Ch3.1@5182.72,1335.84 ; v2(5257,1603.84) R13_Ch3.1@5257,1637.56
  Signal Layer 1 w10: v2(5068,5073.13) 5085,5056.13 5085,4993.56 5127.72,4950.84 5398.72,4950.84 5462,4887.56 5462,3970.13 5326,3834.13 5326,3473.13 5222,3369.13 5222,1785.84 5063,1626.84 5063,1379.84 5092,1350.84 5134,1350.84 v2(5149,1335.84)
  Bottom Layer w15: v2(5068,5073.13) 5082.5,5087.63 5082.5,5128.4 5114.32,5160.22 5121.64,5167.54 5411.41,5167.54 5477,5233.13 5477,5305.02 5465,5317.02 R47_Ch3.1@5465,5340.27 ; v2(5149,1335.84) 5161.5,1348.34 5208.86,1348.34 5244,1383.49 5244,1590.84 v2(5257,1603.84)
  other v2: 5465,5321.84
CS-_Ch4: R13_Ch4.1 R16_Ch4.1 R26_Ch4.1 R28_Ch4.1 R47_Ch4.1 | length 5341
  Top Layer w15: v2(6630,5073.05) R28_Ch4.1@6630,5110.19 ; v2(6711,1335.76) R16_Ch4.1@6744.72,1335.76 ; v2(6819,1603.76) R13_Ch4.1@6819,1637.48
  Signal Layer 1 w10: v2(6630,5073.05) 6647,5056.05 6647,4993.48 6689.72,4950.76 6960.72,4950.76 7024,4887.48 7024,3970.05 6888,3834.05 6888,3473.05 6784,3369.05 6784,1785.76 6625,1626.76 6625,1379.76 6654,1350.76 6696,1350.76 v2(6711,1335.76)
  Bottom Layer w15: v2(6630,5073.05) 6644.5,5087.55 6644.5,5128.32 6676.32,5160.14 6683.64,5167.46 6973.41,5167.46 7039,5233.06 7039,5304.94 7027,5316.94 R47_Ch4.1@7027,5340.19 ; v2(6711,1335.76) 6723.5,1348.26 6770.86,1348.26 6806,1383.41 6806,1590.76 v2(6819,1603.76)
  other v2: 7027,5321.76
CS-_Ch5: R13_Ch5.1 R16_Ch5.1 R26_Ch5.1 R28_Ch5.1 R47_Ch5.1 | length 5341
  Top Layer w15: v2(8585.7,5072.97) R28_Ch5.1@8585.7,5110.11 ; v2(8666.7,1335.69) R16_Ch5.1@8700.42,1335.69 ; v2(8774.7,1603.69) R13_Ch5.1@8774.7,1637.4
  Signal Layer 1 w10: v2(8585.7,5072.97) 8602.7,5055.97 8602.7,4993.4 8645.42,4950.69 8916.42,4950.69 8979.7,4887.4 8979.7,3969.97 8843.7,3833.97 8843.7,3472.97 8739.7,3368.97 8739.7,1785.69 8580.7,1626.69 8580.7,1379.69 8609.7,1350.69 8651.7,1350.69 v2(8666.7,1335.69)
  Bottom Layer w15: v2(8585.7,5072.97) 8600.2,5087.47 8600.2,5128.24 8632.02,5160.06 8639.35,5167.39 8929.11,5167.39 8994.7,5232.98 8994.7,5304.86 8982.7,5316.86 R47_Ch5.1@8982.7,5340.11 ; v2(8666.7,1335.69) 8679.2,1348.19 8726.56,1348.19 8761.7,1383.33 8761.7,1590.69 v2(8774.7,1603.69)
  other v2: 8982.7,5321.69
CS-_Ch6: R13_Ch6.1 R16_Ch6.1 R26_Ch6.1 R28_Ch6.1 R47_Ch6.1 | length 5341
  Top Layer w15: v2(10147.7,5072.89) R28_Ch6.1@10147.7,5110.03 ; v2(10228.7,1335.61) R16_Ch6.1@10262.42,1335.61 ; v2(10336.7,1603.61) R13_Ch6.1@10336.7,1637.32
  Signal Layer 1 w10: v2(10147.7,5072.89) 10164.7,5055.89 10164.7,4993.32 10207.42,4950.61 10478.42,4950.61 10541.7,4887.32 10541.7,3969.89 10405.7,3833.89 10405.7,3472.89 10301.7,3368.89 10301.7,1785.61 10142.7,1626.61 10142.7,1379.61 10171.7,1350.61 10213.7,1350.61 v2(10228.7,1335.61)
  Bottom Layer w15: v2(10147.7,5072.89) 10162.2,5087.39 10162.2,5128.16 10194.02,5159.98 10201.35,5167.31 10491.11,5167.31 10556.7,5232.9 10556.7,5304.78 10544.7,5316.78 R47_Ch6.1@10544.7,5340.03 ; v2(10228.7,1335.61) 10241.2,1348.11 10288.56,1348.11 10323.7,1383.25 10323.7,1590.61 v2(10336.7,1603.61)
  other v2: 10544.7,5321.61
CS-_Ch7: R13_Ch7.1 R16_Ch7.1 R26_Ch7.1 R28_Ch7.1 R47_Ch7.1 | length 5341
  Top Layer w15: v2(11709.7,5072.81) R28_Ch7.1@11709.7,5109.95 ; v2(11790.7,1335.53) R16_Ch7.1@11824.42,1335.53 ; v2(11898.7,1603.53) R13_Ch7.1@11898.7,1637.24
  Signal Layer 1 w10: v2(11709.7,5072.81) 11726.7,5055.81 11726.7,4993.24 11769.42,4950.53 12040.42,4950.53 12103.7,4887.24 12103.7,3969.81 11967.7,3833.81 11967.7,3472.81 11863.7,3368.81 11863.7,1785.53 11704.7,1626.53 11704.7,1379.53 11733.7,1350.53 11775.7,1350.53 v2(11790.7,1335.53)
  Bottom Layer w15: v2(11709.7,5072.81) 11724.2,5087.31 11724.2,5128.08 11756.02,5159.91 11763.35,5167.23 12053.11,5167.23 12118.7,5232.82 12118.7,5304.7 12106.7,5316.7 R47_Ch7.1@12106.7,5339.95 ; v2(11790.7,1335.53) 11803.2,1348.03 11850.56,1348.03 11885.7,1383.17 11885.7,1590.53 v2(11898.7,1603.53)
  other v2: 12106.7,5321.53
CS-_Ch8: R13_Ch8.1 R16_Ch8.1 R26_Ch8.1 R28_Ch8.1 R47_Ch8.1 | length 5341
  Top Layer w15: v2(13271.7,5072.73) R28_Ch8.1@13271.7,5109.87 ; v2(13352.7,1335.45) R16_Ch8.1@13386.42,1335.45 ; v2(13460.7,1603.45) R13_Ch8.1@13460.7,1637.17
  Signal Layer 1 w10: v2(13271.7,5072.73) 13288.7,5055.73 13288.7,4993.16 13331.42,4950.45 13602.42,4950.45 13665.7,4887.16 13665.7,3969.73 13529.7,3833.73 13529.7,3472.73 13425.7,3368.73 13425.7,1785.45 13266.7,1626.45 13266.7,1379.45 13295.7,1350.45 13337.7,1350.45 v2(13352.7,1335.45)
  Bottom Layer w15: v2(13271.7,5072.73) 13286.2,5087.23 13286.2,5128.01 13318.02,5159.83 13325.35,5167.15 13615.11,5167.15 13680.7,5232.74 13680.7,5304.63 13668.7,5316.63 R47_Ch8.1@13668.7,5339.87 ; v2(13352.7,1335.45) 13365.2,1347.95 13412.56,1347.95 13447.7,1383.09 13447.7,1590.45 v2(13460.7,1603.45)
  other v2: 13668.7,5321.45
DACA: R192_Ch1.1 R192_Ch2.1 R192_Ch3.1 R192_Ch4.1 R192_Ch5.1 R192_Ch6.1 R192_Ch7.1 R192_Ch8.1 R218_Ch1.2 R218_Ch2.2 R218_Ch3.2 R218_Ch4.2 R218_Ch5.2 R218_Ch6.2 R218_Ch7.2 R218_Ch8.2 R221.1 | length 18485.2
  Top Layer w10: v2(5706.49,7311) 5747.02,7311 R221.1@5751.74,7315.72
  Signal Layer 1 w10: v2(1949,6178) 1999,6228 3460.92,6228 v2(3511,6177.92) 3561,6227.92 5022.92,6227.92 5072.06,6178.78 v2@5073,6177.84 ; v2(5071.35,6178.07) 5121.35,6228.07 6583.27,6228.07 v2@6633.35,6177.99 ; v2(6635.24,6177.52) 6685.24,6227.52 8540.87,6227.52 v2(8590.94,6177.44) 8640.94,6227.44 10102.87,6227.44 v2(10152.94,6177.36) 10202.94,6227.36 11664.87,6227.36 v2(11714.94,6177.28) 11764.94,6227.28 13226.87,6227.28 v2(13276.94,6177.2)
  Signal Layer 2 w10: v2(1949,6178) 2008,6237 2888,6237 3176,6525 5034,6525 5706.49,7197.49 v2(5706.49,7311)
  Bottom Layer w15: R192_Ch1.1@1922,5884.62 1948.62,5911.24 R218_Ch1.2@1948.62,6122.66 ; R218_Ch1.2@1940.6,6114.64 R218_Ch1.2@1948.62,6122.66 ; v2(1949,6178) 1948.62,6177.62 R218_Ch1.2@1948.62,6122.66 ; R192_Ch2.1@3484,5884.54 3510.62,5911.17 R218_Ch2.2@3510.62,6122.58 ; R218_Ch2.2@3502.6,6114.56 R218_Ch2.2@3510.62,6122.58 ; v2(3511,6177.92) 3510.62,6177.54 R218_Ch2.2@3510.62,6122.58 ; R192_Ch3.1@5044.35,5884.69 5070.97,5911.31 R218_Ch3.2@5070.97,6122.73 ; R218_Ch3.2@5062.95,6114.71 R218_Ch3.2@5070.97,6122.73 ; v2(5071.35,6178.07) 5070.97,6177.69 R218_Ch3.2@5070.97,6122.73 ; R192_Ch4.1@6608.24,5884.14 6634.87,5910.76 R218_Ch4.2@6634.87,6122.18 ; R218_Ch4.2@6626.84,6114.16 R218_Ch4.2@6634.87,6122.18 ; v2(6635.24,6177.52) 6634.87,6177.14 R218_Ch4.2@6634.87,6122.18 ; R192_Ch5.1@8563.94,5884.06 8590.57,5910.69 R218_Ch5.2@8590.57,6121.94 ; R218_Ch5.2@8582.62,6114 R218_Ch5.2@8590.57,6121.94 ; v2(8590.94,6177.44) 8590.57,6177.06 R218_Ch5.2@8590.57,6121.94 ; R192_Ch6.1@10125.94,5883.98 10152.57,5910.61 R218_Ch6.2@10152.57,6121.87 ; R218_Ch6.2@10144.62,6113.92 R218_Ch6.2@10152.57,6121.87 ; v2(10152.94,6177.36) 10152.57,6176.98 R218_Ch6.2@10152.57,6121.87 ; R192_Ch7.1@11687.94,5883.91 11714.57,5910.53 R218_Ch7.2@11714.57,6121.79 ; R218_Ch7.2@11706.62,6113.84 R218_Ch7.2@11714.57,6121.79 ; v2(11714.94,6177.28) 11714.57,6176.91 R218_Ch7.2@11714.57,6121.79 ; R192_Ch8.1@13249.94,5883.83 13276.57,5910.45 R218_Ch8.2@13276.57,6121.71 ; R218_Ch8.2@13268.62,6113.76 R218_Ch8.2@13276.57,6121.71 ; v2(13276.94,6177.2) 13276.57,6176.83 R218_Ch8.2@13276.57,6121.71
DCM_Boost_Ch1: R174_Ch1.1 U24_Ch1.3 U29_Ch1.3 | length 2610.7
  Top Layer w15: R174_Ch1.1@1618,5439 v2(1679,5439)
  Signal Layer 1 w10: v2(1679,5439) 1589,5439 1541,5391 1541,4994 1604,4931 1604,3648 1747,3505 v2(1945,3505)
  Bottom Layer w15: v2(1679,5439) 1712,5439 1731.61,5419.39 U29_Ch1.3@1731.61,5391.2 ; U24_Ch1.3@1922,3629.04 1922,3528 v2(1945,3505)
DCM_Boost_Ch2: R174_Ch2.1 U24_Ch2.3 U29_Ch2.3 | length 2607.3
  Top Layer w15: R174_Ch2.1@3180,5438.92 v2(3241,5438.92)
  Signal Layer 1 w10: v2(3241,5438.92) 3153.92,5438.92 3105,5390 3105,4988 3166,4927 3166,3647.92 3309,3504.92 v2(3507,3504.92)
  Bottom Layer w15: v2(3241,5438.92) 3274,5438.92 3293.61,5419.31 U29_Ch2.3@3293.61,5391.13 ; U24_Ch2.3@3484,3628.96 3484,3527.92 v2(3507,3504.92)
DCM_Boost_Ch3: R174_Ch3.1 U24_Ch3.3 U29_Ch3.3 | length 2614.4
  Top Layer w15: R174_Ch3.1@4742,5438.84 v2(4803,5438.84)
  Signal Layer 1 w10: v2(4803,5438.84) 4703.84,5438.84 4667,5402 4667,4993.92 4728,4932.92 4728,3647.84 4871,3504.84 v2(5069,3504.84)
  Bottom Layer w15: v2(4803,5438.84) 4836,5438.84 4855.61,5419.23 U29_Ch3.3@4855.61,5391.05 ; U24_Ch3.3@5046,3628.88 5046,3527.84 v2(5069,3504.84)
DCM_Boost_Ch4: R174_Ch4.1 U24_Ch4.3 U29_Ch4.3 | length 2607.9
  Top Layer w15: R174_Ch4.1@6304,5438.76 v2(6365,5438.76)
  Signal Layer 1 w10: v2(6365,5438.76) 6279.76,5438.76 6227,5386 6227,4999 6290,4936 6290,3647.76 6433,3504.76 v2(6631,3504.76)
  Bottom Layer w15: v2(6365,5438.76) 6398,5438.76 6417.61,5419.15 U29_Ch4.3@6417.61,5390.97 ; U24_Ch4.3@6608,3628.8 6608,3527.76 v2(6631,3504.76)
DCM_Boost_Ch5: R174_Ch5.1 U24_Ch5.3 U29_Ch5.3 | length 2610.4
  Top Layer w15: R174_Ch5.1@8259.7,5438.69 v2(8320.7,5438.69)
  Signal Layer 1 w10: v2(8320.7,5438.69) 8229.39,5438.69 8184,5393.3 8184,4996 8245.7,4934.3 8245.7,3647.69 8388.7,3504.69 v2(8586.7,3504.69)
  Bottom Layer w15: v2(8320.7,5438.69) 8353.7,5438.69 8373.32,5419.07 U29_Ch5.3@8373.32,5390.89 ; U24_Ch5.3@8563.7,3628.72 8563.7,3527.68 v2(8586.7,3504.69)
DCM_Boost_Ch6: R174_Ch6.1 U24_Ch6.3 U29_Ch6.3 | length 2613.1
  Top Layer w15: R174_Ch6.1@9821.7,5438.61 v2(9882.7,5438.61)
  Signal Layer 1 w10: v2(9882.7,5438.61) 9789.61,5438.61 9744,5393 9744,4977 9807.7,4913.3 9807.7,3647.61 9950.7,3504.61 v2(10148.7,3504.61)
  Bottom Layer w15: v2(9882.7,5438.61) 9915.7,5438.61 9935.32,5418.99 U29_Ch6.3@9935.32,5390.81 ; U24_Ch6.3@10125.7,3628.64 10125.7,3527.61 v2(10148.7,3504.61)
DCM_Boost_Ch7: R174_Ch7.1 U24_Ch7.3 U29_Ch7.3 | length 2615.4
  Top Layer w15: R174_Ch7.1@11383.7,5438.53 v2(11444.7,5438.53)
  Signal Layer 1 w10: v2(11444.7,5438.53) 11350.53,5438.53 11304,5392 11304,4987 11369.7,4921.3 11369.7,3647.53 11512.7,3504.53 v2(11710.7,3504.53)
  Bottom Layer w15: v2(11444.7,5438.53) 11477.7,5438.53 11497.32,5418.91 U29_Ch7.3@11497.32,5390.73 ; U24_Ch7.3@11687.7,3628.56 11687.7,3527.53 v2(11710.7,3504.53)
DCM_Boost_Ch8: R174_Ch8.1 U24_Ch8.3 U29_Ch8.3 | length 2608.8
  Top Layer w15: R174_Ch8.1@12945.7,5438.45 v2(13006.7,5438.45)
  Signal Layer 1 w10: v2(13006.7,5438.45) 12922.35,5438.45 12867,5383.1 12867,4982.4 12931.7,4917.7 12931.7,3647.45 13074.7,3504.45 v2(13272.7,3504.45)
  Bottom Layer w15: v2(13006.7,5438.45) 13039.7,5438.45 13059.32,5418.83 U29_Ch8.3@13059.32,5390.65 ; U24_Ch8.3@13249.7,3628.49 13249.7,3527.45 v2(13272.7,3504.45)
DCM_Buck_Ch1: R173_Ch1.1 U2_Ch1.3 U29_Ch1.5 | length 2203.3
  Top Layer w15: R173_Ch1.1@1554,5439 1554,5405 1572,5387 1765,5387 1782.8,5369.2 v2(1782.8,5347.33)
  Signal Layer 1 w10: v2(1718.29,3626) 1639,3705.29 1639,4905 1714,4980 1714,5307.18 1754.16,5347.33 v2(1782.8,5347.33)
  Bottom Layer w15: v2(1718.29,3626) U2_Ch1.3@1718.29,3655.41 ; v2(1782.8,5347.33) U29_Ch1.5@1782.8,5391.2
DCM_Buck_Ch2: R173_Ch2.1 U2_Ch2.3 U29_Ch2.5 | length 2203.3
  Top Layer w15: R173_Ch2.1@3116,5438.92 3116,5404.92 3134,5386.92 3327,5386.92 3344.8,5369.13 v2(3344.8,5347.26)
  Signal Layer 1 w10: v2(3280.29,3625.92) 3201,3705.21 3201,4927.47 3280.29,5006.76 3280.29,5311.39 3316.16,5347.26 v2(3344.8,5347.26)
  Bottom Layer w15: v2(3280.29,3625.92) U2_Ch2.3@3280.29,3655.33 ; v2(3344.8,5347.26) U29_Ch2.5@3344.8,5391.13
DCM_Buck_Ch3: R173_Ch3.1 U2_Ch3.3 U29_Ch3.5 | length 2203.3
  Top Layer w15: R173_Ch3.1@4678,5438.84 4678,5404.84 4696,5386.84 4889,5386.84 4906.8,5369.05 v2(4906.8,5347.18)
  Signal Layer 1 w10: v2(4842.29,3625.84) 4763,3705.13 4763,4933.39 4841,5011.39 4841,5310.02 4878.16,5347.18 v2(4906.8,5347.18)
  Bottom Layer w15: v2(4842.29,3625.84) U2_Ch3.3@4842.29,3655.25 ; v2(4906.8,5347.18) U29_Ch3.5@4906.8,5391.05
DCM_Buck_Ch4: R173_Ch4.1 U2_Ch4.3 U29_Ch4.5 | length 2203.3
  Top Layer w15: R173_Ch4.1@6240,5438.76 6240,5404.76 6258,5386.76 6451,5386.76 6468.8,5368.97 v2(6468.8,5347.1)
  Signal Layer 1 w10: v2(6404.29,3625.76) 6325,3705.06 6325,4936 6396,5007 6396,5302.94 6440.16,5347.1 v2(6468.8,5347.1)
  Bottom Layer w15: v2(6404.29,3625.76) U2_Ch4.3@6404.29,3655.17 ; v2(6468.8,5347.1) U29_Ch4.5@6468.8,5390.97
DCM_Buck_Ch5: R173_Ch5.1 U2_Ch5.3 U29_Ch5.5 | length 2203.3
  Top Layer w15: R173_Ch5.1@8195.7,5438.69 8195.7,5404.69 8213.7,5386.69 8406.7,5386.69 8424.5,5368.89 v2(8424.5,5347.02)
  Signal Layer 1 w10: v2(8359.99,3625.69) 8280.7,3704.98 8280.7,4911.7 8359,4990 8359,5310.16 8395.86,5347.02 v2(8424.5,5347.02)
  Bottom Layer w15: v2(8359.99,3625.69) U2_Ch5.3@8359.99,3655.09 ; v2(8424.5,5347.02) U29_Ch5.5@8424.5,5390.89
DCM_Buck_Ch6: R173_Ch6.1 U2_Ch6.3 U29_Ch6.5 | length 2203.3
  Top Layer w15: R173_Ch6.1@9757.7,5438.61 9757.7,5404.61 9775.7,5386.61 9968.7,5386.61 9986.5,5368.81 v2(9986.5,5346.94)
  Signal Layer 1 w10: v2(9921.99,3625.61) 9842.7,3704.9 9842.7,4912.7 9916,4986 9916,5305.08 9957.86,5346.94 v2(9986.5,5346.94)
  Bottom Layer w15: v2(9921.99,3625.61) U2_Ch6.3@9921.99,3655.02 ; v2(9986.5,5346.94) U29_Ch6.5@9986.5,5390.81
DCM_Buck_Ch7: R173_Ch7.1 U2_Ch7.3 U29_Ch7.5 | length 2203.3
  Top Layer w15: R173_Ch7.1@11319.7,5438.53 11319.7,5404.53 11337.7,5386.53 11530.7,5386.53 11548.5,5368.73 v2(11548.5,5346.86)
  Signal Layer 1 w10: v2(11483.99,3625.53) 11404.7,3704.82 11404.7,4924.7 11477,4997 11477,5304 11519.86,5346.86 v2(11548.5,5346.86)
  Bottom Layer w15: v2(11483.99,3625.53) U2_Ch7.3@11483.99,3654.94 ; v2(11548.5,5346.86) U29_Ch7.5@11548.5,5390.73
DCM_Buck_Ch8: R173_Ch8.1 U2_Ch8.3 U29_Ch8.5 | length 2203.3
  Top Layer w15: R173_Ch8.1@12881.7,5438.45 12881.7,5404.45 12899.7,5386.45 13092.7,5386.45 13110.5,5368.65 v2(13110.5,5346.78)
  Signal Layer 1 w10: v2(13045.99,3625.45) 12966.7,3704.74 12966.7,4922.7 13037,4993 13037,5301.93 13081.86,5346.78 v2(13110.5,5346.78)
  Bottom Layer w15: v2(13045.99,3625.45) U2_Ch8.3@13045.99,3654.86 ; v2(13110.5,5346.78) U29_Ch8.5@13110.5,5390.65
DGND: C14_Ch1.1 C14_Ch2.1 C14_Ch3.1 C14_Ch4.1 C14_Ch5.1 C14_Ch6.1 C14_Ch7.1 C14_Ch8.1 C64.2 C72.1 C73.2 C74.2 C85.2 C93.1 C94.2 C95.2 C122_Ch1.1 C122_Ch2.1 C122_Ch3.1 C122_Ch4.1 C122_Ch5.1 C122_Ch6.1 C122_Ch7.1 C122_Ch8.1 C123.2 C124.2 C125.2 C126.2 C138.2 C139.2 C140.2 C141.2 C143.2 C148.2 C149.2 C163.2 C165.2 D14.1 D18.1 D33.1 J5.7 J5.10 J5.13 J5.16 J5.19 J5.22 J5.29 J5.35 J5.38 J5.46 J5.47 J5.65 J5.83 J5.97 J5.111 J6.135 J6.157 J6.179 R152.2 S1.2 S2.2 S4.9 S4.10 S4.11 S4.12 S4.13 S4.14 S4.15 S4.16 S5.9 S5.10 S5.11 S5.12 S5.13 S5.14 S5.15 S5.16 S6.2 TP36.1 TP38.1 TP40.1 TP41.1 U2_Ch1.2 U2_Ch2.2 U2_Ch3.2 U2_Ch4.2 U2_Ch5.2 U2_Ch6.2 U2_Ch7.2 U2_Ch8.2 U12.25 U16.25 U24_Ch1.2 U24_Ch2.2 U24_Ch3.2 U24_Ch4.2 U24_Ch5.2 U24_Ch6.2 U24_Ch7.2 U24_Ch8.2 U25.2 U26.5 U26.8 U27.5 U27.8 U28.3 U28.4 U28.5 U28.6 U28.8 U31.5 Y1.2 Y2.2 | length 52832.8
  Top Layer w6: U28.8@7218,6841.27 7181.74,6841.27 7164.25,6858.76 v2(7164.25,6892.73) 7191.54,6920.01 U28.3@7218,6920.01 U28.4@7218,6904.26 ; U28.6@7218,6872.77 U28.5@7218,6888.52 U28.4@7218,6904.26 ; 7268.75,6904.26 U28.4@7218,6904.26
  Top Layer w10: 4192.59,7396.7 4204.66,7384.63 4204.66,7364.5 4216.25,7352.91 U12.25@4251.13,7352.91 ; 7268.75,6904.26 7279.11,6904.26 7293.5,6918.66 C123.2@7293.5,7008.01 ; J6.135@8542.76,7542.7 J6.135@8542.98,7542.48 ; J6.157@8889.21,7542.7 J6.157@8889.43,7542.48 ; J6.179@9235.67,7542.7 J6.179@9235.89,7542.48 ; 10834.29,7396.38 10846.36,7384.32 10846.36,7364.19 10857.95,7352.59 U16.25@10892.83,7352.59
  Top Layer w15: C73.2@4135.11,7452.51 4136.78,7452.51 4192.59,7396.7 ; D33.1@7102.35,8030 D33.1@7104.85,8032.5 7111.35,8039 7179,8039 v2(7202,8016) ; U27.8@8320.2,7155.27 8320.2,7110.5 8329.78,7100.92 8458.27,7100.92 8470.2,7112.85 U27.5@8470.2,7155.27 ; v2(8543,7439) J6.135@8543,7542.46 ; v2(8889.46,7439) J6.157@8889.46,7542.46 ; v2(9235.91,7439) J6.179@9235.91,7542.46 ; C94.2@10776.82,7452.19 10778.49,7452.19 10834.29,7396.38
  Top Layer w20: v1(1618.59,8084.11) R152.2@1618.59,8145 ; v1(1618.59,8205.89) R152.2@1618.59,8145 ; v1(1667.7,8145) R152.2@1618.59,8145 ; v1(2601.5,7991.7) D18.1@2601.5,8037.6 ; v1(2992.18,8040.5) C139.2@3042,8040.5 ; v1(3042,7988.33) C139.2@3042,8040.5 ; v1(3109.53,7988.33) C138.2@3109.53,8040.5 ; v1(3184.33,7950) C165.2@3236.5,7950 ; U25.2@3191.4,8054 3160.2,8054 3146.71,8040.5 C138.2@3109.53,8040.5 ; v1(3380,7974.33) C163.2@3380,8026.5 v1(3432.18,8026.5) ; D14.1@3935.11,7741.5 v1(3981.01,7741.5) ; C74.2@4069.11,7452.51 4069.53,7452.92 v2(4069.53,7495.63) ; TP38.1@4079,7732.42 4125.41,7686.01 C148.2@4179,7686.01 4202.3,7662.7 Y1.2@4253.71,7662.7 ; C73.2@4135.11,7452.51 4135.53,7452.92 v2(4135.53,7495.63) ; C64.2@4265.71,7829.11 v2(4265.71,7870.63) ; C72.1@4706.61,7656.01 v2(4706.61,7693.55) ; S1.2@4807.81,7765.01 v2(4807.81,7816.91) ; v2(5805.75,7434.78) J5.7@5805.75,7542.7 J5.7@5805.82,7542.78 ; J5.10@5837.17,7676.48 J5.10@5837.25,7676.56 v2(5837.25,7784.48) ; v2(5900.24,7434.78) J5.13@5900.24,7542.7 J5.13@5900.31,7542.78 ; J5.16@5931.66,7676.48 J5.16@5931.73,7676.56 v2(5931.73,7784.48) ; v2(5994.73,7434.78) J5.19@5994.73,7542.7 J5.19@5994.8,7542.78 ; J5.22@6026.15,7676.48 J5.22@6026.22,7676.56 v2(6026.22,7784.48) ; v2(6152.21,7434.78) J5.29@6152.21,7542.7 J5.29@6152.21,7542.7 ; v2(6246.7,7434.78) J5.35@6246.7,7542.7 J5.35@6246.7,7542.7 ; J5.38@6278.12,7676.48 J5.38@6278.19,7676.56 v2(6278.19,7784.48) ; J5.46@6404.1,7676.48 J5.46@6404.18,7676.56 v2(6404.18,7784.48) ; v2(6435.67,7434.78) J5.47@6435.67,7542.7 J5.47@6435.75,7542.78 ; v2(6845.12,7434.78) J5.65@6845.12,7542.7 J5.65@6845.19,7542.78 ; J5.83@7128.66,7542.78 J5.83@7128.58,7542.7 7129,7542.29 v2(7129,7447) ; v2(7349.06,7434.78) J5.97@7349.06,7542.7 J5.97@7349.13,7542.78 ; v2(7499,7955) 7499,7986.15 S6.2@7529.77,8016.92 ; v2(7532.76,7918.07) C126.2@7580.52,7918.07 ; v2(7569.53,7434.78) J5.111@7569.53,7542.7 J5.111@7569.6,7542.78 ; v1(7694.78,6830.69) 7694.78,6785.2 C124.2@7696.28,6783.69 C124.2@7696.78,6783.2 ; U26.5@7992.09,6920.7 v1(8050,6920.7) ; U26.8@7992.09,7070.7 8009.7,7070.7 v1(8043,7104) ; v1(8272.73,7155.27) U27.8@8320.2,7155.27 ; v1(8562.21,6862.97) C125.2@8607.71,6862.97 C125.2@8609.71,6864.97 ; C95.2@10710.82,7452.19 10711.23,7452.61 v2(10711.23,7495.32) ; TP40.1@10713,7738.62 10764.61,7687.01 C149.2@10820.02,7687.01 10843.64,7663.39 Y2.2@10894.41,7663.39 ; C94.2@10776.82,7452.19 10777.23,7452.61 v2(10777.23,7495.32) ; C85.2@10906.84,7828.21 C85.2@10907.32,7828.7 v2(10907.32,7868.31) ; C93.1@11348.31,7655.7 v2(11348.31,7693.24) ; S2.2@11449.51,7764.7 v2(11449.51,7816.6) ; C139.2@3042,8040.5 C138.2@3109.53,8040.5
  Signal Layer 2 w15: v2(1760,3671) 1763.43,3674.43 1819.34,3674.43 ; v2(1766.11,3603.11) 1819.02,3603.11 1833.98,3618.07 1833.98,3659.8 1819.34,3674.43 ; v2(3322,3670.92) 3325.43,3674.36 3381.34,3674.36 ; v2(3328.11,3603.04) 3381.02,3603.04 3395.98,3617.99 3395.98,3659.72 3381.34,3674.36 ; v2(4884,3670.84) 4887.43,3674.28 4943.34,3674.28 ; v2(4890.11,3602.96) 4943.02,3602.96 4957.98,3617.91 4957.98,3659.64 4943.34,3674.28 ; v2(6317.75,6746.39) 6017.37,6446 3205,6446 2325,5566 2325,5493.51 2237,5405.51 2237,5126 1964,4853 1964,3945 1849,3830 1849,3704.09 1819.34,3674.43 ; v2(6354,6604) 6095,6345 4650,6345 3896,5591 3896,5497 3798,5399 3798,5140 3526,4868 3526,3944.92 3411,3829.92 3411,3704.02 3381.34,3674.36 ; v2(6446,3670.76) 6449.43,3674.2 6505.34,3674.2 ; v2(6452.11,3602.88) 6505.02,3602.88 6519.98,3617.83 6519.98,3659.56 6505.34,3674.2 ; v2(6457,6569) 5456,5568 5456,5509 5359,5412 5359,5145 5088,4874 5088,3944.84 4973,3829.84 4973,3703.94 4943.34,3674.28 ; v2(6637,6582) 7152,6067 7152,5707 7007,5562 7007,5488 6919,5400 6919,5146 6650,4877 6650,3944.76 6535,3829.76 6535,3703.86 6505.34,3674.2 ; v2(6755,6622) 7977,5400 7977,5151 8272,4856 8272,3961.2 8378,3855.2 8378,3694.39 v2(8401.7,3670.69) 8405.14,3674.12 8461.04,3674.12 8475.68,3659.48 8475.68,3617.76 8460.72,3602.8 v2(8407.81,3602.8) ; v2(6857,6673.2) 7095.2,6435 9210.14,6435 9651,5994.14 9651,5059 9834,4876 9834,3961.12 9940,3855.12 9940,3694.31 v2(9963.7,3670.61) 9967.14,3674.04 10023.04,3674.04 10037.68,3659.4 10037.68,3617.68 10022.72,3602.72 v2(9969.81,3602.72) ; v2(6972,6733) 7171,6534 9306,6534 9521,6319 10925,6319 11210,6034 11210,5070 11396,4884 11396,3961.04 11502,3855.04 11502,3694.23 v2(11525.7,3670.53) 11529.14,3673.96 11585.04,3673.96 11599.68,3659.33 11599.68,3617.6 11584.72,3602.64 v2(11531.81,3602.64) ; v2(7023,6834) 7230,6627 9374,6627 9581,6420 12163,6420 12751,5832 12751,5089 12958,4882 12958,3960.96 13064,3854.96 13064,3694.15 v2(13087.7,3670.45) 13091.14,3673.88 13147.04,3673.88 13161.68,3659.25 13161.68,3617.52 13146.72,3602.56 v2(13093.81,3602.56)
  Signal Layer 2 w20: v2(9963.7,3670.61) v2@9967.89,3670.61
  Bottom Layer w8: C122_Ch1.1@1871,3647.06 1887.68,3663.74 1939.49,3663.74 1947.59,3655.64 U24_Ch1.2@1947.59,3629.04 ; C122_Ch2.1@3433,3646.98 3449.68,3663.66 3501.49,3663.66 3509.59,3655.56 U24_Ch2.2@3509.59,3628.96 ; C122_Ch3.1@4995,3646.9 5011.68,3663.58 5063.49,3663.58 5071.59,3655.48 U24_Ch3.2@5071.59,3628.88 ; C122_Ch4.1@6557,3646.82 6573.68,3663.5 6625.49,3663.5 6633.59,3655.4 U24_Ch4.2@6633.59,3628.8 ; C122_Ch5.1@8512.7,3646.75 8529.38,3663.43 8581.19,3663.43 8589.29,3655.32 U24_Ch5.2@8589.29,3628.72 ; C122_Ch6.1@10074.7,3646.67 10091.38,3663.35 10143.19,3663.35 10151.29,3655.24 U24_Ch6.2@10151.29,3628.64 ; C122_Ch7.1@11636.7,3646.59 11653.38,3663.27 11705.19,3663.27 11713.29,3655.16 U24_Ch7.2@11713.29,3628.56 ; C122_Ch8.1@13198.7,3646.51 13215.38,3663.19 13267.19,3663.19 13275.29,3655.08 U24_Ch8.2@13275.29,3628.49
  Bottom Layer w15: C14_Ch1.1@1684.56,3587 1750,3587 v2(1766.11,3603.11) 1858.11,3603.11 1871,3616 C122_Ch1.1@1871,3647.06 ; U2_Ch1.2@1718.29,3681 1750,3681 v2(1760,3671) ; C14_Ch2.1@3246.56,3586.92 3312,3586.92 v2(3328.11,3603.04) 3420.11,3603.04 3433,3615.92 C122_Ch2.1@3433,3646.98 ; U2_Ch2.2@3280.29,3680.92 3312,3680.92 v2(3322,3670.92) ; C14_Ch3.1@4808.56,3586.84 4874,3586.84 v2(4890.11,3602.96) 4982.11,3602.96 4995,3615.84 C122_Ch3.1@4995,3646.9 ; U2_Ch3.2@4842.29,3680.84 4874,3680.84 v2(4884,3670.84) ; C14_Ch4.1@6370.56,3586.76 6436,3586.76 v2(6452.11,3602.88) 6544.11,3602.88 6557,3615.77 C122_Ch4.1@6557,3646.82 ; U2_Ch4.2@6404.29,3680.76 6436,3680.76 v2(6446,3670.76) ; C14_Ch5.1@8326.26,3586.69 8391.7,3586.69 v2(8407.81,3602.8) 8499.81,3602.8 8512.7,3615.69 C122_Ch5.1@8512.7,3646.75 ; U2_Ch5.2@8359.99,3680.69 8391.7,3680.69 v2(8401.7,3670.69) ; C14_Ch6.1@9888.26,3586.61 9953.7,3586.61 v2(9969.81,3602.72) 10061.81,3602.72 10074.7,3615.61 C122_Ch6.1@10074.7,3646.67 ; U2_Ch6.2@9921.99,3680.61 9953.7,3680.61 v2(9963.7,3670.61) ; C14_Ch7.1@11450.26,3586.53 11515.7,3586.53 v2(11531.81,3602.64) 11623.81,3602.64 11636.7,3615.53 C122_Ch7.1@11636.7,3646.59 ; U2_Ch7.2@11483.99,3680.53 11515.7,3680.53 v2(11525.7,3670.53) ; C14_Ch8.1@13012.26,3586.45 13077.7,3586.45 v2(13093.81,3602.56) 13185.81,3602.56 13198.7,3615.45 C122_Ch8.1@13198.7,3646.51 ; U2_Ch8.2@13045.99,3680.45 13077.7,3680.45 v2(13087.7,3670.45)
  Bottom Layer w20: v1(1869.42,7943.58) C143.2@1918.5,7943.58
  other v1: 8179.69,6317.97 8279.69,6317.97 8379.69,6317.97 8479.69,6317.97 8876.2,6849.97 8976.2,6849.97 9076.2,6849.97 9176.2,6849.97 2151,7947 1776.35,8208.53 1829.07,8208.53 1881.79,8208.53
DIN1: R102.2 R277.1 TP12.1 | length 3597.3
  Top Layer w10: TP12.1@4307.11,8020.01 4376.11,7951.01 R102.2@4376.11,7584.63 ; R277.1@6830.01,7315.88 6830.01,7227.99 v2(6844,7214)
  Bottom Layer w10: TP12.1@4307.11,8020.01 4376.11,7951.01 4376.11,7686.59 4451,7611.7 5149,7611.7 5546.7,7214 v2(6844,7214)
DIN2: R133.2 R284.1 TP18.1 | length 4757.9
  Top Layer w10: v2(7033,7189) R284.1@7033.01,7315.88 ; TP18.1@10948.82,8019.7 11017.82,7950.7 R133.2@11017.82,7584.32
  Bottom Layer w10: v2(7033,7189) 8009.41,7189 8372.41,7552 9922,7552 9996.71,7626.71 v2(11018.7,7626.71)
